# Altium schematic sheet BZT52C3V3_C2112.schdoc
size 127 x 101 mm
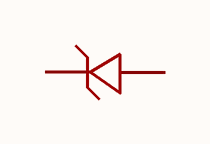
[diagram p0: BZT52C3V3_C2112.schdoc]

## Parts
ZD?  bzt52c3v3_c2112  [SOD-123_L2.8-W1.8-LS3.7-RD]  (value not drawn)

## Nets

Not connected (* = marked no-connect by the designer): ZD? 1(K) 2(A)

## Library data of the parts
ZD? = bzt52c3v3_c2112: 二极管配置:1个独立式;稳压值(标称值):3.3V;稳压值(范围值):3.1V~3.5V;耗散功率(Pd):500mW;; Manufacturer: CJ(江苏长电/长晶); AddInBom: yes; ModelId: 7884390a25fb4c08947731ebfba7e3f8; ModelTransform: 144.8816,62.992,0,0,0,0,0,0,0; Diode Configuration: 1个独立式; Zener Voltage(Nom): 3.3V; Reverse Leakage Current (Ir): 5uA; Pd - Power Dissipation: 500mW; Impedance(Zzt): 95Ω; Impedance(Zzk): 600Ω; Operating Junction Temperature Range: -55℃~+150℃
